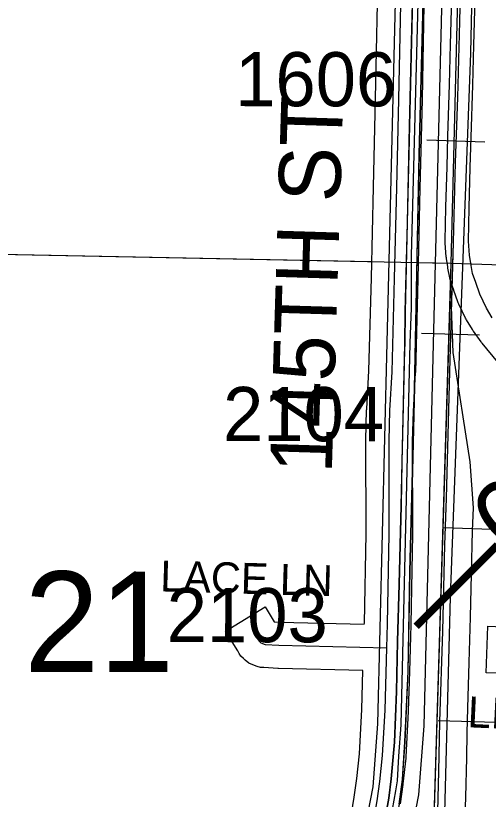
# Model space of a CAD drawing. Extents: x -132.8 to -73.3, y -60 to -26.
# Drawn here: x -125.183 to -124.572, y -41.962 to -40.948 of the extents above; entities that cross this region are included whole.
import ezdxf

# ---------------------------------------------------------------- set-up
doc = ezdxf.new("R2010")
doc.units = 0
for name, color, linetype in [('tdCoDivCarto', 7, 'Continuous'), ('tdCoInt', 7, 'Continuous'), ('tdCoIntCL', 7, 'Continuous'), ('tdCoIntRte', 7, 'Continuous'), ('tdCoPrimary', 7, 'Continuous'), ('tdCoRRCL', 7, 'Continuous'), ('tdCoSecRdNmbr', 7, 'Continuous'), ('tdCoSecRdTxt', 7, 'Continuous'), ('tdCoSecRteBand', 7, 'Continuous'), ('tdCoSecRteCL', 7, 'Continuous'), ('tdCoSectLine', 7, 'Continuous'), ('tdCoSectLinePart', 7, 'Continuous'), ('tdCoSectNmbr', 7, 'Continuous'), ('tdCoSurfGravel', 7, 'Continuous'), ('tdStHwyIntRefPost1', 7, 'Continuous')]:
    doc.layers.add(name, color=color, linetype=linetype)

msp = doc.modelspace()

# ---------------------------------------------------------------- linework, layer by layer
at = {"layer": 'tdCoDivCarto'}
for p, q in [((-124.6683, -40.8659), (-124.6713, -40.9823)), ((-124.6574, -40.9965), (-124.6542, -40.8806)), ((-124.6713, -40.9823), (-124.6735, -41.0908)), ((-124.6606, -41.1279), (-124.6574, -40.9965)), ((-124.6735, -41.0908), (-124.6765, -41.2161)), ((-124.6636, -41.2593), (-124.6606, -41.1279)), ((-124.6765, -41.2161), (-124.6792, -41.3315)), ((-124.6665, -41.4108), (-124.6636, -41.2593)), ((-124.6792, -41.3315), (-124.6799, -41.3729)), ((-124.6801, -41.3801), (-124.6826, -41.4902)), ((-124.6801, -41.3801), (-124.6826, -41.4902)), ((-124.6799, -41.3729), (-124.6801, -41.3801)), ((-124.6692, -41.5375), (-124.6665, -41.4108)), ((-124.6826, -41.4902), (-124.6834, -41.5256)), ((-124.6834, -41.5256), (-124.6846, -41.5826)), ((-124.6727, -41.6672), (-124.6692, -41.5375)), ((-124.6846, -41.5826), (-124.6871, -41.6837)), ((-124.6752, -41.7967), (-124.6727, -41.6672)), ((-124.6871, -41.6837), (-124.6893, -41.7577)), ((-124.6893, -41.7577), (-124.6905, -41.8225)), ((-124.6793, -41.8877), (-124.6752, -41.7967)), ((-124.6905, -41.8225), (-124.693, -41.8881)), ((-124.6826, -41.9365), (-124.6793, -41.8877)), ((-124.693, -41.8881), (-124.6972, -41.9355)), ((-124.6972, -41.9355), (-124.7006, -41.9604)), ((-124.6867, -41.9681), (-124.6826, -41.9365)), ((-124.7006, -41.9604), (-124.713, -42.0297))]:
    msp.add_line(p, q, dxfattribs=at)
for points in [[(-124.6239, -39.2678), (-124.6272, -39.3767), (-124.6309, -39.5064), (-124.6343, -39.6267), (-124.6373, -39.7468), (-124.6407, -39.861), (-124.6442, -39.9712), (-124.6474, -40.098), (-124.6501, -40.1979), (-124.6533, -40.3123), (-124.6565, -40.427), (-124.659, -40.5337), (-124.6627, -40.6615), (-124.6659, -40.7549), (-124.6683, -40.8659), (-124.6713, -40.9823), (-124.6735, -41.0908), (-124.6765, -41.2161), (-124.6792, -41.3315), (-124.6799, -41.3729), (-124.6801, -41.3801)], [(-124.6248, -39.2985), (-124.6272, -39.3767), (-124.6309, -39.5064), (-124.6343, -39.6267), (-124.6373, -39.7468), (-124.6407, -39.861), (-124.6442, -39.9712), (-124.6474, -40.098), (-124.6501, -40.1979), (-124.6533, -40.3123), (-124.6565, -40.427), (-124.659, -40.5337), (-124.6627, -40.6615), (-124.6659, -40.7549), (-124.6683, -40.8659), (-124.6713, -40.9823), (-124.6735, -41.0908), (-124.6765, -41.2161), (-124.6792, -41.3315), (-124.6799, -41.3729), (-124.6801, -41.3801)], [(-124.6248, -39.2985), (-124.6272, -39.3767), (-124.6309, -39.5064), (-124.6343, -39.6267), (-124.6373, -39.7468), (-124.6407, -39.861), (-124.6442, -39.9712), (-124.6474, -40.098), (-124.6501, -40.1979), (-124.6533, -40.3123), (-124.6565, -40.427), (-124.659, -40.5337), (-124.6627, -40.6615), (-124.6659, -40.7549), (-124.6683, -40.8659), (-124.6713, -40.9823), (-124.6735, -41.0908), (-124.6765, -41.2161), (-124.6792, -41.3315), (-124.6799, -41.3729), (-124.6801, -41.3801)], [(-124.7449, -42.2545), (-124.7255, -42.1607), (-124.6978, -42.0243), (-124.6867, -41.9681), (-124.6826, -41.9365), (-124.6793, -41.8877), (-124.6752, -41.7967), (-124.6727, -41.6672), (-124.6692, -41.5375), (-124.6665, -41.4108), (-124.6636, -41.2593), (-124.6606, -41.1279), (-124.6574, -40.9965), (-124.6542, -40.8806), (-124.6532, -40.8421)], [(-124.7449, -42.2545), (-124.7255, -42.1607), (-124.6978, -42.0243), (-124.6867, -41.9681), (-124.6826, -41.9365), (-124.6793, -41.8877), (-124.6752, -41.7967), (-124.6727, -41.6672), (-124.6692, -41.5375), (-124.6665, -41.4108), (-124.6636, -41.2593), (-124.6606, -41.1279), (-124.6574, -40.9965), (-124.6542, -40.8806), (-124.6532, -40.8421)], [(-124.7449, -42.2545), (-124.7255, -42.1607), (-124.6978, -42.0243), (-124.6867, -41.9681), (-124.6826, -41.9365), (-124.6793, -41.8877), (-124.6752, -41.7967), (-124.6727, -41.6672), (-124.6692, -41.5375), (-124.6665, -41.4108), (-124.6636, -41.2593), (-124.6606, -41.1279), (-124.6574, -40.9965), (-124.6542, -40.8806), (-124.6532, -40.8421)], [(-124.6801, -41.3801), (-124.6826, -41.4902)], [(-124.6801, -41.3801), (-124.6826, -41.4902)], [(-124.6826, -41.4902), (-124.6834, -41.5256), (-124.6846, -41.5826), (-124.6871, -41.6837), (-124.6893, -41.7577), (-124.6905, -41.8225), (-124.693, -41.8881), (-124.6972, -41.9355), (-124.7006, -41.9604), (-124.713, -42.0297), (-124.7214, -42.0689), (-124.7317, -42.1248), (-124.7482, -42.2013), (-124.7622, -42.2669)], [(-124.6826, -41.4902), (-124.6834, -41.5256), (-124.6846, -41.5826), (-124.6871, -41.6837), (-124.6893, -41.7577), (-124.6905, -41.8225), (-124.693, -41.8881), (-124.6972, -41.9355), (-124.7006, -41.9604), (-124.713, -42.0297), (-124.7214, -42.0689), (-124.7317, -42.1248), (-124.7482, -42.2013), (-124.7622, -42.2669)], [(-124.6826, -41.4902), (-124.6834, -41.5256), (-124.6846, -41.5826), (-124.6871, -41.6837), (-124.6893, -41.7577), (-124.6905, -41.8225), (-124.693, -41.8881), (-124.6972, -41.9355), (-124.7006, -41.9604), (-124.713, -42.0297), (-124.7214, -42.0689), (-124.7317, -42.1248), (-124.7482, -42.2013), (-124.7622, -42.2669)]]:
    msp.add_lwpolyline(points, dxfattribs=at)
at = {"layer": 'tdCoInt'}
for points in [[(-124.8021, -42.7539), (-124.8139, -42.7197), (-124.8275, -42.6566), (-124.8324, -42.6207), (-124.8354, -42.5778), (-124.8351, -42.5439), (-124.832, -42.5093), (-124.8247, -42.4617), (-124.7845, -42.2624), (-124.7589, -42.1427), (-124.7207, -41.946), (-124.7146, -41.8642), (-124.7027, -41.3713), (-124.6757, -40.2788), (-124.6465, -39.2641), (-124.6408, -39.0846), (-124.6387, -38.9782), (-124.6391, -38.9204), (-124.6436, -38.853), (-124.666, -38.5908), (-124.6763, -38.4345), (-124.6792, -38.3683), (-124.6793, -38.3624)], [(-124.7463, -42.7316), (-124.7558, -42.704), (-124.7683, -42.6464), (-124.7726, -42.6147), (-124.7753, -42.5752), (-124.7751, -42.5468), (-124.7724, -42.5167), (-124.7656, -42.4719), (-124.7258, -42.2746), (-124.7002, -42.1547), (-124.6616, -41.9562), (-124.6546, -41.8669), (-124.6427, -41.3729), (-124.6157, -40.2804), (-124.5865, -39.2656), (-124.5809, -39.0862), (-124.5787, -38.9786), (-124.5791, -38.9183), (-124.5838, -38.8478), (-124.6062, -38.5862), (-124.6164, -38.4312), (-124.6192, -38.3666), (-124.6193, -38.3639)]]:
    msp.add_lwpolyline(points, dxfattribs=at)
at = {"layer": 'tdCoIntCL'}
msp.add_lwpolyline([(-124.7973, -42.4827), (-124.7972, -42.4821), (-124.7749, -42.3657), (-124.7748, -42.3653), (-124.7551, -42.2685), (-124.7544, -42.2651), (-124.7295, -42.1487), (-124.7001, -41.9991), (-124.6912, -41.9511), (-124.689, -41.9379), (-124.6873, -41.9063), (-124.6846, -41.8656), (-124.6837, -41.8286), (-124.6727, -41.3721), (-124.672, -41.3492), (-124.6713, -41.3263), (-124.6709, -41.2786), (-124.6709, -41.2687), (-124.6709, -41.2587), (-124.6562, -40.6862)], dxfattribs=at)
at = {"layer": 'tdCoIntRte'}
for points in [[(-124.6687, -40.8659), (-124.6717, -40.9823), (-124.6739, -41.0908), (-124.6769, -41.2161), (-124.6796, -41.3315), (-124.6803, -41.3729), (-124.6838, -41.5256), (-124.685, -41.5826), (-124.6875, -41.6837), (-124.6897, -41.7577), (-124.6909, -41.8225), (-124.6934, -41.8881), (-124.6976, -41.9355), (-124.701, -41.9604), (-124.7133, -42.0297), (-124.7217, -42.0689), (-124.7321, -42.1248), (-124.7486, -42.2013), (-124.7626, -42.2669), (-124.7666, -42.2859), (-124.7836, -42.3655), (-124.7845, -42.3693), (-124.7891, -42.3899), (-124.7892, -42.3904)], [(-124.6687, -40.8659), (-124.6717, -40.9823), (-124.6739, -41.0908), (-124.6769, -41.2161), (-124.6796, -41.3315), (-124.6803, -41.3729), (-124.6838, -41.5256), (-124.685, -41.5826), (-124.6875, -41.6837), (-124.6897, -41.7577), (-124.6909, -41.8225), (-124.6934, -41.8881), (-124.6976, -41.9355), (-124.701, -41.9604), (-124.7133, -42.0297), (-124.7217, -42.0689), (-124.7321, -42.1248), (-124.7486, -42.2013), (-124.7626, -42.2669), (-124.7666, -42.2859), (-124.7836, -42.3655), (-124.7845, -42.3693), (-124.7891, -42.3899), (-124.7892, -42.3904)], [(-124.6871, -41.9681), (-124.6829, -41.9365), (-124.6797, -41.8877), (-124.6755, -41.7967), (-124.6731, -41.6672), (-124.6696, -41.5375), (-124.6669, -41.4108), (-124.6639, -41.2593), (-124.661, -41.1279), (-124.6578, -40.9965), (-124.6546, -40.8806)], [(-124.6871, -41.9681), (-124.6829, -41.9365), (-124.6797, -41.8877), (-124.6755, -41.7967), (-124.6731, -41.6672), (-124.6696, -41.5375), (-124.6669, -41.4108), (-124.6639, -41.2593), (-124.661, -41.1279), (-124.6578, -40.9965), (-124.6546, -40.8806)]]:
    msp.add_lwpolyline(points, dxfattribs=at)
at = {"layer": 'tdCoPrimary'}
msp.add_line((-124.6801, -41.3801), (-124.6826, -41.4902), dxfattribs=at)
msp.add_line((-124.6801, -41.3801), (-124.6826, -41.4902), dxfattribs=at)
for points in [[(-124.6248, -39.2985), (-124.6272, -39.3767), (-124.6309, -39.5064), (-124.6343, -39.6267), (-124.6373, -39.7468), (-124.6407, -39.861), (-124.6442, -39.9712), (-124.6474, -40.098), (-124.6501, -40.1979), (-124.6533, -40.3123), (-124.6565, -40.427), (-124.659, -40.5337), (-124.6627, -40.6615), (-124.6659, -40.7549), (-124.6683, -40.8659), (-124.6713, -40.9823), (-124.6735, -41.0908), (-124.6765, -41.2161), (-124.6792, -41.3315), (-124.6799, -41.3729), (-124.6801, -41.3801)], [(-124.6248, -39.2985), (-124.6272, -39.3767), (-124.6309, -39.5064), (-124.6343, -39.6267), (-124.6373, -39.7468), (-124.6407, -39.861), (-124.6442, -39.9712), (-124.6474, -40.098), (-124.6501, -40.1979), (-124.6533, -40.3123), (-124.6565, -40.427), (-124.659, -40.5337), (-124.6627, -40.6615), (-124.6659, -40.7549), (-124.6683, -40.8659), (-124.6713, -40.9823), (-124.6735, -41.0908), (-124.6765, -41.2161), (-124.6792, -41.3315), (-124.6799, -41.3729), (-124.6801, -41.3801)], [(-124.7449, -42.2545), (-124.7255, -42.1607), (-124.6978, -42.0243), (-124.6867, -41.9681), (-124.6826, -41.9365), (-124.6793, -41.8877), (-124.6752, -41.7967), (-124.6727, -41.6672), (-124.6692, -41.5375), (-124.6665, -41.4108), (-124.6636, -41.2593), (-124.6606, -41.1279), (-124.6574, -40.9965), (-124.6542, -40.8806), (-124.6532, -40.8421)], [(-124.7449, -42.2545), (-124.7255, -42.1607), (-124.6978, -42.0243), (-124.6867, -41.9681), (-124.6826, -41.9365), (-124.6793, -41.8877), (-124.6752, -41.7967), (-124.6727, -41.6672), (-124.6692, -41.5375), (-124.6665, -41.4108), (-124.6636, -41.2593), (-124.6606, -41.1279), (-124.6574, -40.9965), (-124.6542, -40.8806), (-124.6532, -40.8421)], [(-124.6683, -40.8659), (-124.6713, -40.9823), (-124.6735, -41.0908), (-124.6765, -41.2161), (-124.6792, -41.3315), (-124.6799, -41.3729), (-124.6801, -41.3801), (-124.6826, -41.4902), (-124.6834, -41.5256), (-124.6846, -41.5826), (-124.6871, -41.6837), (-124.6893, -41.7577), (-124.6905, -41.8225), (-124.693, -41.8881), (-124.6972, -41.9355), (-124.7006, -41.9604), (-124.713, -42.0297)], [(-124.6867, -41.9681), (-124.6826, -41.9365), (-124.6793, -41.8877), (-124.6752, -41.7967), (-124.6727, -41.6672), (-124.6692, -41.5375), (-124.6665, -41.4108), (-124.6636, -41.2593), (-124.6606, -41.1279), (-124.6574, -40.9965), (-124.6542, -40.8806)], [(-124.6826, -41.4902), (-124.6834, -41.5256), (-124.6846, -41.5826), (-124.6871, -41.6837), (-124.6893, -41.7577), (-124.6905, -41.8225), (-124.693, -41.8881), (-124.6972, -41.9355), (-124.7006, -41.9604), (-124.713, -42.0297), (-124.7214, -42.0689), (-124.7317, -42.1248), (-124.7482, -42.2013), (-124.7622, -42.2669)], [(-124.6826, -41.4902), (-124.6834, -41.5256), (-124.6846, -41.5826), (-124.6871, -41.6837), (-124.6893, -41.7577), (-124.6905, -41.8225), (-124.693, -41.8881), (-124.6972, -41.9355), (-124.7006, -41.9604), (-124.713, -42.0297), (-124.7214, -42.0689), (-124.7317, -42.1248), (-124.7482, -42.2013), (-124.7622, -42.2669)]]:
    msp.add_lwpolyline(points, dxfattribs=at)
at = {"layer": 'tdCoRRCL'}
for p, q in [((-124.6511, -41.1092), (-124.5761, -41.1115)), ((-124.6581, -41.3591), (-124.5831, -41.3614)), ((-124.6302, -41.6105), (-124.5552, -41.6131)), ((-124.6367, -41.8601), (-124.5617, -41.8623))]:
    msp.add_line(p, q, dxfattribs=at)
for points in [[(-124.5644, -39.5828), (-124.595, -40.997), (-124.6213, -41.6999), (-124.6444, -42.5874), (-124.6174, -42.7017), (-124.5989, -42.7795), (-124.5745, -42.87), (-124.3645, -43.4103), (-124.2879, -43.6206), (-124.2072, -43.8562), (-124.0007, -44.409), (-123.8311, -44.9246), (-123.7542, -45.1238), (-123.6724, -45.2553), (-123.3407, -45.7294), (-123.3115, -45.7601), (-123.2156, -45.9536), (-123.186, -46.0285), (-123.1192, -46.4325), (-123.0248, -47.1717), (-122.9661, -47.7049)], [(-124.6074, -40.8812), (-124.6092, -40.9559), (-124.6118, -41.0545), (-124.6145, -41.1383), (-124.6171, -41.2419), (-124.6221, -41.4086), (-124.6263, -41.573), (-124.6284, -41.6327), (-124.6312, -41.7444), (-124.6347, -41.8619), (-124.636, -41.9261), (-124.6373, -41.9772)], [(-124.6074, -40.8812), (-124.6092, -40.9559), (-124.6118, -41.0545), (-124.6145, -41.1383), (-124.6171, -41.2419), (-124.6196, -41.3252), (-124.6177, -41.384), (-124.5957, -41.5253), (-124.5915, -41.585), (-124.5926, -41.6149), (-124.594, -41.6707), (-124.5954, -41.7265), (-124.5971, -41.7852), (-124.5988, -41.844), (-124.5995, -41.8761), (-124.6002, -41.9082), (-124.6015, -41.9593), (-124.6025, -41.9963)]]:
    msp.add_lwpolyline(points, dxfattribs=at)
at = {"layer": 'tdCoSecRteBand'}
for points in [[(-124.5596, -41.3964), (-124.5798, -41.3721), (-124.5804, -41.3713), (-124.581, -41.3705), (-124.591, -41.3567), (-124.5917, -41.3557), (-124.5924, -41.3545), (-124.5999, -41.342), (-124.6006, -41.3408), (-124.6012, -41.3396), (-124.6099, -41.3214), (-124.6106, -41.32), (-124.6111, -41.3185), (-124.6163, -41.3038), (-124.6164, -41.3035), (-124.6165, -41.3033), (-124.6205, -41.2915), (-124.6211, -41.2897), (-124.6215, -41.2877), (-124.6241, -41.2749), (-124.6242, -41.2741), (-124.6243, -41.2733), (-124.6259, -41.2625), (-124.626, -41.2615), (-124.6261, -41.2605), (-124.6274, -41.2425), (-124.6275, -41.241), (-124.6275, -41.2396), (-124.6265, -41.1964), (-124.6265, -41.1964), (-124.6265, -41.1963), (-124.625, -41.1441), (-124.624, -41.1047), (-124.624, -41.1046), (-124.624, -41.1045), (-124.6219, -41.0373), (-124.6207, -40.9859), (-124.6207, -40.9858), (-124.6207, -40.9857), (-124.6188, -40.9251)], [(-124.75, -41.9891), (-124.745, -41.9594), (-124.7417, -41.9352), (-124.7384, -41.9032), (-124.7352, -41.8456), (-124.7338, -41.7954), (-124.8431, -41.7928), (-124.8435, -41.7927), (-124.844, -41.7927), (-124.862, -41.7917), (-124.8664, -41.7915), (-124.8706, -41.79), (-124.876, -41.788), (-124.8815, -41.786), (-124.8859, -41.7821), (-124.8883, -41.7799), (-124.8915, -41.777), (-124.8938, -41.7733), (-124.8958, -41.7701), (-124.9115, -41.7445), (-124.8604, -41.7131), (-124.8485, -41.7324), (-124.8412, -41.7328), (-124.7321, -41.7354), (-124.7321, -41.7352), (-124.732, -41.7341), (-124.7298, -41.6187), (-124.7301, -41.4984), (-124.7301, -41.498), (-124.73, -41.4976), (-124.7291, -41.4582), (-124.729, -41.4577), (-124.729, -41.4571), (-124.7261, -41.4076), (-124.7229, -41.2875), (-124.7202, -41.1702), (-124.7202, -41.1702), (-124.7202, -41.1702), (-124.7175, -41.0558), (-124.715, -40.933)], [(-124.655, -40.9343), (-124.6575, -41.0571), (-124.6575, -41.0571), (-124.6575, -41.0572), (-124.6602, -41.1716), (-124.6629, -41.289), (-124.6629, -41.289), (-124.6629, -41.2891), (-124.6661, -41.4096), (-124.6661, -41.4101), (-124.6662, -41.4106), (-124.6691, -41.4602), (-124.6701, -41.4987), (-124.6698, -41.6189), (-124.6698, -41.6192), (-124.6698, -41.6195), (-124.672, -41.7354), (-124.672, -41.7356), (-124.672, -41.7357), (-124.6729, -41.7669), (-124.6736, -41.7968), (-124.6738, -41.7968), (-124.6752, -41.8477), (-124.6753, -41.8481), (-124.6753, -41.8485), (-124.6785, -41.9072), (-124.6785, -41.9079), (-124.6786, -41.9086), (-124.6821, -41.9419), (-124.6821, -41.9424), (-124.6822, -41.9429), (-124.6856, -41.968)], [(-124.5446, -41.7992), (-124.5746, -41.7982), (-124.5725, -41.7382), (-124.5425, -41.7393)]]:
    msp.add_lwpolyline(points, dxfattribs=at)
at = {"layer": 'tdCoSecRteCL'}
for points in [[(-124.7029, -41.7661), (-124.702, -41.7349), (-124.6998, -41.619), (-124.7001, -41.4984), (-124.6991, -41.4589), (-124.6961, -41.4089), (-124.6929, -41.2883), (-124.6902, -41.1709), (-124.6875, -41.0565), (-124.685, -40.9336), (-124.6833, -40.8528), (-124.6838, -40.8306), (-124.6843, -40.8212), (-124.687, -40.8106), (-124.6914, -40.8002), (-124.6966, -40.7918), (-124.7025, -40.7844), (-124.7099, -40.7783), (-124.7168, -40.7741), (-124.7262, -40.7709), (-124.7368, -40.7694), (-124.7632, -40.7687), (-124.792, -40.7672), (-124.8063, -40.7655)], [(-124.5666, -41.3392), (-124.5741, -41.3266), (-124.5828, -41.3085), (-124.5881, -41.2937), (-124.5921, -41.2819), (-124.5946, -41.2691), (-124.5962, -41.2583), (-124.5975, -41.2403), (-124.5965, -41.1971), (-124.5951, -41.1449), (-124.594, -41.1054), (-124.5919, -41.0382), (-124.5907, -40.9866), (-124.5889, -40.926)], [(-124.8702, -41.7544), (-124.8682, -41.7576), (-124.8658, -41.7598), (-124.8604, -41.7618), (-124.8424, -41.7628), (-124.7029, -41.7661)], [(-124.8522, -42.5454), (-124.8431, -42.5247), (-124.8303, -42.4937), (-124.8209, -42.4653), (-124.8073, -42.4096), (-124.7841, -42.2979), (-124.7787, -42.272), (-124.7597, -42.1822), (-124.7338, -42.0614), (-124.7205, -41.9945), (-124.7153, -41.964), (-124.7119, -41.9388), (-124.7084, -41.9055), (-124.7052, -41.8468), (-124.7029, -41.7661)]]:
    msp.add_lwpolyline(points, dxfattribs=at)
at = {"layer": 'tdCoSectLine'}
for points in [[(-124.6196, -41.2685), (-124.5949, -40.2729)], [(-125.6168, -41.2488), (-124.6196, -41.2685)], [(-124.6503, -42.2654), (-124.6196, -41.2685)], [(-124.6196, -41.2685), (-123.619, -41.3013)]]:
    msp.add_lwpolyline(points, dxfattribs=at)
at = {"layer": 'tdCoSectLinePart'}
for points in [[(-125.6168, -41.2488), (-124.7228, -41.2665)], [(-124.6628, -41.2677), (-124.6251, -41.2684)], [(-124.6503, -42.2654), (-124.6203, -41.293)]]:
    msp.add_lwpolyline(points, dxfattribs=at)
at = {"layer": 'tdCoSurfGravel'}
for points in [[(-124.7787, -42.272), (-124.7597, -42.1822), (-124.7338, -42.0614), (-124.7205, -41.9945), (-124.7153, -41.964), (-124.7119, -41.9388), (-124.7084, -41.9055), (-124.7052, -41.8468), (-124.7029, -41.7661), (-124.702, -41.7349), (-124.6998, -41.619), (-124.7001, -41.4984), (-124.6991, -41.4589), (-124.6961, -41.4089), (-124.6929, -41.2883), (-124.6902, -41.1709), (-124.6875, -41.0565), (-124.685, -40.9336)], [(-124.5666, -41.3392), (-124.5741, -41.3266), (-124.5828, -41.3085), (-124.5881, -41.2937), (-124.5921, -41.2819), (-124.5946, -41.2691), (-124.5962, -41.2583), (-124.5975, -41.2403), (-124.5965, -41.1971), (-124.5951, -41.1449), (-124.594, -41.1054), (-124.5919, -41.0382), (-124.5907, -40.9866), (-124.5889, -40.926)], [(-124.8702, -41.7544), (-124.8682, -41.7576), (-124.8658, -41.7598), (-124.8604, -41.7618), (-124.8424, -41.7628), (-124.7029, -41.7661)]]:
    msp.add_lwpolyline(points, dxfattribs=at)

# ---------------------------------------------------------------- texts
at = {"layer": 'tdCoSecRdNmbr'}
for s, rotation, p in [('1606', 359.9066, (-124.8991, -41.0655)), ('2104', 359.9067, (-124.9148, -41.4986)), ('2103', 359.9065, (-124.9876, -41.7586))]:
    msp.add_text(s, height=0.07, rotation=rotation, dxfattribs=at).set_placement(p)
at = {"layer": 'tdCoSecRdTxt'}
for s, height, rotation, p in [('145TH ST', 0.08, 88.2534, (-124.7742, -41.5412)), ('LACE LN', 0.04, 358.3693, (-124.9963, -41.693)), ('LIBERTY LN', 0.04, 357.3754, (-124.5991, -41.8687))]:
    msp.add_text(s, height=height, rotation=rotation, dxfattribs=at).set_placement(p)
at = {"layer": 'tdCoSectNmbr'}
msp.add_text('21', height=0.13, rotation=359.9063, dxfattribs=at).set_placement((-125.1716, -41.7971))
at = {"layer": 'tdStHwyIntRefPost1'}
msp.add_text('‒‒63', height=0.1, rotation=45, dxfattribs=at).set_placement((-124.6389, -41.7643))

doc.saveas('drawing.dxf')
